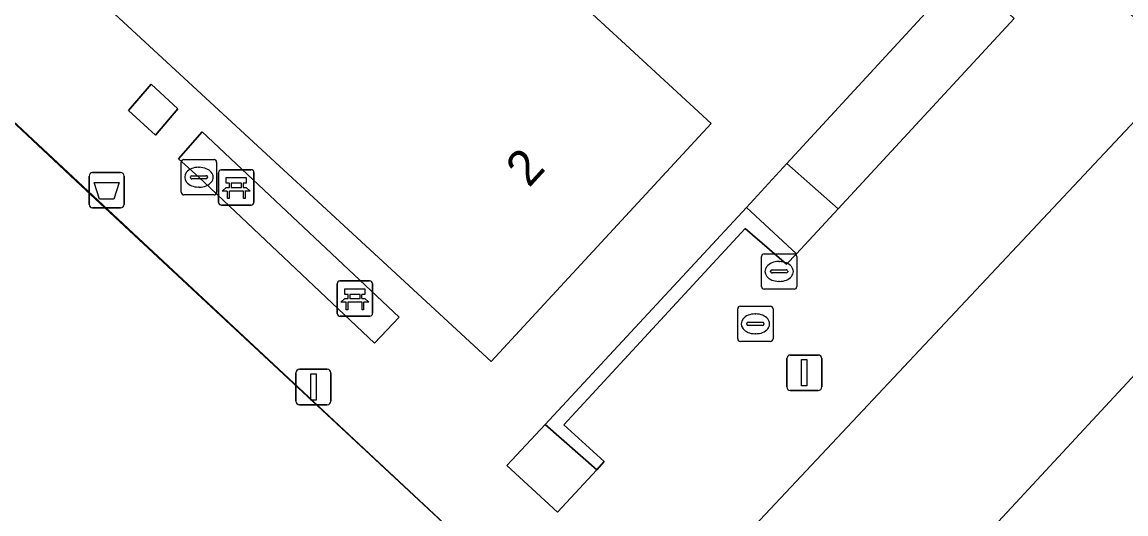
# Model space of a CAD drawing. Extents: x 155640 to 156811, y 382821 to 384049.
# Drawn here: x 156220.39 to 156251.61, y 383284.66 to 383298.57 of the extents above; entities that cross this region are included whole.
import ezdxf

# ---------------------------------------------------------------- set-up
doc = ezdxf.new("R2010")
doc.units = 0
for name, color, linetype in [('IMGEO_Afvalbak', 7, 'Continuous'), ('IMGEO_Bank', 7, 'Continuous'), ('IMGEO_Groenvoorziening', 7, 'Continuous'), ('IMGEO_Haag', 7, 'Continuous'), ('IMGEO_Hek', 7, 'Continuous'), ('IMGEO_Kolk', 7, 'Continuous'), ('IMGEO_Lichtmast', 7, 'Continuous'), ('IMGEO_Pand', 7, 'Continuous'), ('IMGEO_Pand_nummerreeks', 7, 'Continuous'), ('IMGEO_Rioolput', 7, 'Continuous'), ('IMGEO_Terreindeel_halfverhard', 7, 'Continuous'), ('IMGEO_Voetpad_op_trap', 7, 'Continuous'), ('IMGEO_Voetpad_open', 7, 'Continuous')]:
    doc.layers.add(name, color=color, linetype=linetype)

msp = doc.modelspace()

# ---------------------------------------------------------------- linework, layer by layer
at = {"layer": 'IMGEO_Afvalbak'}
for p, q in [((156222.283, 383293.417), (156222.283, 383294.217)), ((156222.283, 383294.217), (156222.283, 383293.417)), ((156222.383, 383294.317), (156223.173, 383294.317)), ((156223.173, 383294.317), (156222.383, 383294.317)), ((156223.273, 383294.217), (156223.273, 383293.417)), ((156223.273, 383293.417), (156223.273, 383294.217)), ((156223.173, 383293.317), (156222.383, 383293.317)), ((156222.383, 383293.317), (156223.173, 383293.317))]:
    msp.add_line(p, q, dxfattribs=at)
msp.add_lwpolyline([(156222.426, 383294.031), (156223.13, 383294.031), (156222.981, 383293.561), (156222.575, 383293.561), (156222.426, 383294.031)], dxfattribs=at)
for centre, start, end in [((156222.383, 383294.217), 90, 180), ((156222.383, 383294.217), 90, 180), ((156223.173, 383294.217), 0, 90), ((156223.173, 383294.217), 360, 90), ((156222.383, 383293.417), 180, 270), ((156222.383, 383293.417), 180, 270), ((156223.173, 383293.417), 270, 0), ((156223.173, 383293.417), 270, 0)]:
    msp.add_arc(centre, 0.1, start, end, dxfattribs=at)
at = {"layer": 'IMGEO_Bank'}
for p, q in [((156225.946, 383293.471), (156225.946, 383294.312)), ((156225.946, 383294.312), (156225.946, 383293.471)), ((156226.021, 383294.396), (156226.862, 383294.396)), ((156226.862, 383294.396), (156226.021, 383294.396)), ((156226.946, 383294.321), (156226.946, 383293.48)), ((156226.946, 383293.48), (156226.946, 383294.321)), ((156226.255, 383293.902), (156226.255, 383294.008)), ((156226.299, 383294.008), (156226.299, 383293.902)), ((156226.587, 383294.014), (156226.305, 383294.014)), ((156226.305, 383293.896), (156226.587, 383293.896)), ((156226.593, 383293.902), (156226.593, 383294.008)), ((156226.637, 383294.008), (156226.637, 383293.902)), ((156226.643, 383293.794), (156226.25, 383293.794)), ((156226.871, 383293.396), (156226.03, 383293.396)), ((156226.03, 383293.396), (156226.871, 383293.396)), ((156229.301, 383290.328), (156229.301, 383291.169)), ((156229.301, 383291.169), (156229.301, 383290.328)), ((156229.376, 383291.253), (156230.217, 383291.253)), ((156230.217, 383291.253), (156229.376, 383291.253)), ((156230.301, 383291.178), (156230.301, 383290.337)), ((156230.301, 383290.337), (156230.301, 383291.178)), ((156229.61, 383290.759), (156229.61, 383290.865)), ((156229.654, 383290.865), (156229.654, 383290.759)), ((156229.942, 383290.871), (156229.66, 383290.871)), ((156229.948, 383290.759), (156229.948, 383290.865)), ((156229.992, 383290.865), (156229.992, 383290.759)), ((156229.998, 383290.651), (156229.605, 383290.651)), ((156229.66, 383290.753), (156229.942, 383290.753)), ((156230.226, 383290.253), (156229.385, 383290.253)), ((156229.385, 383290.253), (156230.226, 383290.253))]:
    msp.add_line(p, q, dxfattribs=at)
for points in [[(156226.193, 383293.794), (156226.051, 383293.794), (156226.163, 383293.896), (156226.249, 383293.896)], [(156226.249, 383294.014), (156226.163, 383294.014), (156226.163, 383294.175), (156226.726, 383294.175), (156226.726, 383294.014), (156226.643, 383294.014)], [(156226.643, 383293.896), (156226.726, 383293.896), (156226.838, 383293.794), (156226.699, 383293.794)], [(156226.243, 383293.787), (156226.243, 383293.58), (156226.2, 383293.58), (156226.2, 383293.787)], [(156226.693, 383293.787), (156226.693, 383293.58), (156226.649, 383293.58), (156226.649, 383293.787)], [(156229.604, 383290.871), (156229.518, 383290.871), (156229.518, 383291.032), (156230.081, 383291.032), (156230.081, 383290.871), (156229.998, 383290.871)], [(156229.548, 383290.651), (156229.406, 383290.651), (156229.518, 383290.753), (156229.604, 383290.753)], [(156229.598, 383290.644), (156229.598, 383290.437), (156229.555, 383290.437), (156229.555, 383290.644)], [(156229.998, 383290.753), (156230.081, 383290.753), (156230.193, 383290.651), (156230.054, 383290.651)], [(156230.048, 383290.644), (156230.048, 383290.437), (156230.004, 383290.437), (156230.004, 383290.644)]]:
    msp.add_lwpolyline(points, dxfattribs=at)
for centre, radius, start, end in [((156226.024, 383294.318), 0.0779, 92.4484, 184.2845), ((156226.024, 383294.318), 0.0779, 92.4484, 184.2845), ((156226.868, 383294.318), 0.0779, 2.4484, 94.2845), ((156226.868, 383294.318), 0.0779, 2.4484, 94.2845), ((156226.248, 383294.007), 0.00671, 2.8957, 87.1043), ((156226.248, 383293.903), 0.00671, 272.8957, 357.1043), ((156226.305, 383294.007), 0.00671, 92.8957, 177.1043), ((156226.305, 383293.903), 0.00671, 182.8957, 267.1043), ((156226.587, 383294.007), 0.00671, 2.8957, 87.1043), ((156226.587, 383293.903), 0.00671, 272.8957, 357.1043), ((156226.644, 383294.007), 0.00671, 92.8957, 177.1043), ((156226.644, 383293.903), 0.00671, 182.8957, 267.1043), ((156226.193, 383293.787), 0.00671, 2.8957, 87.1043), ((156226.25, 383293.787), 0.00671, 92.8957, 177.1043), ((156226.642, 383293.787), 0.00671, 2.8957, 87.1043), ((156226.699, 383293.787), 0.00671, 92.8957, 177.1043), ((156226.024, 383293.474), 0.0779, 182.4484, 274.2845), ((156226.024, 383293.474), 0.0779, 182.4484, 274.2845), ((156226.868, 383293.474), 0.0779, 272.4484, 4.2845), ((156226.868, 383293.474), 0.0779, 272.4484, 4.2845), ((156229.379, 383291.175), 0.0779, 92.4484, 184.2845), ((156229.379, 383291.175), 0.0779, 92.4484, 184.2845), ((156230.223, 383291.175), 0.0779, 2.4484, 94.2845), ((156230.223, 383291.175), 0.0779, 2.4484, 94.2845), ((156229.603, 383290.864), 0.00671, 2.8957, 87.1043), ((156229.603, 383290.76), 0.00671, 272.8957, 357.1043), ((156229.66, 383290.864), 0.00671, 92.8957, 177.1043), ((156229.66, 383290.76), 0.00671, 182.8957, 267.1043), ((156229.942, 383290.864), 0.00671, 2.8957, 87.1043), ((156229.942, 383290.76), 0.00671, 272.8957, 357.1043), ((156229.999, 383290.864), 0.00671, 92.8957, 177.1043), ((156229.999, 383290.76), 0.00671, 182.8957, 267.1043), ((156229.548, 383290.644), 0.00671, 2.8957, 87.1043), ((156229.605, 383290.644), 0.00671, 92.8957, 177.1043), ((156229.997, 383290.644), 0.00671, 2.8957, 87.1043), ((156230.054, 383290.644), 0.00671, 92.8957, 177.1043), ((156229.379, 383290.331), 0.0779, 182.4484, 274.2845), ((156229.379, 383290.331), 0.0779, 182.4484, 274.2845), ((156230.223, 383290.331), 0.0779, 272.4484, 4.2845), ((156230.223, 383290.331), 0.0779, 272.4484, 4.2845)]:
    msp.add_arc(centre, radius, start, end, dxfattribs=at)
at = {"layer": 'IMGEO_Groenvoorziening'}
for points in [[(156246.051, 383298.946), (156242.012, 383294.574), (156243.464, 383293.287), (156248.449, 383298.674), (156247.041, 383299.984)], [(156242.291, 383292.016), (156240.872, 383293.328), (156235.177, 383287.192), (156236.64, 383285.907), (156236.846, 383286.147), (156235.707, 383287.185), (156240.833, 383292.73), (156242.011, 383291.724)]]:
    msp.add_lwpolyline(points, close=True, dxfattribs=at)
at = {"layer": 'IMGEO_Haag'}
msp.add_lwpolyline([(156242.291, 383292.016), (156240.872, 383293.328), (156235.177, 383287.192), (156236.64, 383285.907), (156236.846, 383286.147), (156235.707, 383287.185), (156240.833, 383292.73), (156242.011, 383291.724)], close=True, dxfattribs=at)
at = {"layer": 'IMGEO_Hek'}
msp.add_lwpolyline([(156214.588, 383300.953), (156234.882, 383282.008)], dxfattribs=at)
at = {"layer": 'IMGEO_Kolk'}
for p, q in [((156224.89, 383293.759), (156224.89, 383294.611)), ((156224.965, 383294.685), (156225.817, 383294.685)), ((156225.891, 383294.611), (156225.891, 383293.759)), ((156225.149, 383294.179), (156225.149, 383294.191)), ((156225.192, 383294.228), (156225.59, 383294.228)), ((156225.378, 383294.465), (156225.403, 383294.465)), ((156225.633, 383294.191), (156225.633, 383294.179)), ((156225.587, 383294.142), (156225.189, 383294.142)), ((156225.401, 383293.905), (156225.376, 383293.905)), ((156225.817, 383293.685), (156224.965, 383293.685)), ((156241.373, 383292.019), (156242.225, 383292.019)), ((156241.298, 383291.093), (156241.298, 383291.945)), ((156241.786, 383291.799), (156241.811, 383291.799)), ((156242.299, 383291.945), (156242.299, 383291.093)), ((156241.557, 383291.513), (156241.557, 383291.525)), ((156241.995, 383291.476), (156241.597, 383291.476)), ((156241.6, 383291.562), (156241.998, 383291.562)), ((156242.041, 383291.525), (156242.041, 383291.513)), ((156241.809, 383291.239), (156241.784, 383291.239)), ((156242.225, 383291.019), (156241.373, 383291.019))]:
    msp.add_line(p, q, dxfattribs=at)
for points in [[(156224.89, 383293.759), (156224.89, 383294.611)], [(156224.965, 383294.685), (156225.817, 383294.685)], [(156225.891, 383294.611), (156225.891, 383293.759)], [(156225.817, 383293.685), (156224.965, 383293.685)], [(156241.373, 383292.019), (156242.225, 383292.019)], [(156241.298, 383291.093), (156241.298, 383291.945)], [(156242.299, 383291.945), (156242.299, 383291.093)], [(156242.225, 383291.019), (156241.373, 383291.019)]]:
    msp.add_lwpolyline(points, dxfattribs=at)
for centre, radius, start, end in [((156224.967, 383294.609), 0.0765, 91.552, 178.448), ((156224.967, 383294.609), 0.0765, 91.552, 178.448), ((156225.815, 383294.609), 0.0765, 1.552, 88.448), ((156225.815, 383294.609), 0.0765, 1.552, 88.448), ((156225.189, 383294.188), 0.0403, 85.8775, 175.7526), ((156225.594, 383294.19), 0.0386, 1.7309, 96.639), ((156225.186, 383294.178), 0.0366, 178.938, 274.7102), ((156225.59, 383294.185), 0.043, 264.8664, 352.4533), ((156224.967, 383293.761), 0.0765, 181.552, 268.448), ((156224.967, 383293.761), 0.0765, 181.552, 268.448), ((156225.815, 383293.761), 0.0765, 271.552, 358.448), ((156225.815, 383293.761), 0.0765, 271.552, 358.448), ((156241.375, 383291.943), 0.0765, 91.552, 178.448), ((156241.375, 383291.943), 0.0765, 91.552, 178.448), ((156242.223, 383291.943), 0.0765, 1.552, 88.448), ((156242.223, 383291.943), 0.0765, 1.552, 88.448), ((156241.597, 383291.522), 0.0403, 85.8775, 175.7526), ((156241.594, 383291.512), 0.0366, 178.938, 274.7102), ((156241.998, 383291.519), 0.043, 264.8664, 352.4533), ((156242.002, 383291.524), 0.0386, 1.7309, 96.639), ((156241.375, 383291.095), 0.0765, 181.552, 268.448), ((156241.375, 383291.095), 0.0765, 181.552, 268.448), ((156242.223, 383291.095), 0.0765, 271.552, 358.448), ((156242.223, 383291.095), 0.0765, 271.552, 358.448)]:
    msp.add_arc(centre, radius, start, end, dxfattribs=at)
for centre, major_axis, ratio, start_param, end_param in [((156225.377, 383294.185), (-0.387, 0.002), 0.722429, 4.712389, 7.853982), ((156225.402, 383294.185), (-0.39, 0.002), 0.717154, 1.570796, 4.712389), ((156241.785, 383291.519), (-0.387, 0.002), 0.722429, 4.712389, 7.853982), ((156241.81, 383291.519), (-0.39, 0.002), 0.717154, 1.570796, 4.712389)]:
    msp.add_ellipse(centre, major_axis=major_axis, ratio=ratio, start_param=start_param, end_param=end_param, dxfattribs=at)
at = {"layer": 'IMGEO_Lichtmast'}
for p, q in [((156242.014, 383288.256), (156242.014, 383289.056)), ((156242.014, 383289.056), (156242.014, 383288.256)), ((156242.114, 383289.156), (156242.904, 383289.156)), ((156242.904, 383289.156), (156242.114, 383289.156)), ((156243.004, 383289.056), (156243.004, 383288.256)), ((156243.004, 383288.256), (156243.004, 383289.056)), ((156228.131, 383287.852), (156228.131, 383288.652)), ((156228.131, 383288.652), (156228.131, 383287.852)), ((156228.231, 383288.752), (156229.021, 383288.752)), ((156229.021, 383288.752), (156228.231, 383288.752)), ((156229.121, 383288.652), (156229.121, 383287.852)), ((156229.121, 383287.852), (156229.121, 383288.652)), ((156242.904, 383288.156), (156242.114, 383288.156)), ((156242.114, 383288.156), (156242.904, 383288.156)), ((156229.021, 383287.752), (156228.231, 383287.752)), ((156228.231, 383287.752), (156229.021, 383287.752))]:
    msp.add_line(p, q, dxfattribs=at)
for points in [[(156242.434, 383289.031), (156242.584, 383289.031), (156242.584, 383288.281), (156242.434, 383288.281), (156242.434, 383289.031)], [(156228.551, 383288.627), (156228.701, 383288.627), (156228.701, 383287.877), (156228.551, 383287.877), (156228.551, 383288.627)]]:
    msp.add_lwpolyline(points, dxfattribs=at)
for centre, start, end in [((156242.114, 383289.056), 90, 180), ((156242.114, 383289.056), 90, 180), ((156242.904, 383289.056), 0, 90), ((156242.904, 383289.056), 360, 90), ((156228.231, 383288.652), 90, 180), ((156228.231, 383288.652), 90, 180), ((156229.021, 383288.652), 0, 90), ((156229.021, 383288.652), 360, 90), ((156242.114, 383288.256), 180, 270), ((156242.114, 383288.256), 180, 270), ((156242.904, 383288.256), 270, 0), ((156242.904, 383288.256), 270, 0), ((156228.231, 383287.852), 180, 270), ((156228.231, 383287.852), 180, 270), ((156229.021, 383287.852), 270, 0), ((156229.021, 383287.852), 270, 0)]:
    msp.add_arc(centre, 0.1, start, end, dxfattribs=at)
at = {"layer": 'IMGEO_Pand'}
msp.add_lwpolyline([(156230.318, 383303.16), (156230.248, 383303.085), (156228.254, 383304.935), (156222.769, 383299.019), (156233.654, 383288.973), (156239.878, 383295.706), (156237.342, 383298.044), (156232.207, 383302.778), (156231.102, 383303.797), (156230.424, 383303.062)], close=True, dxfattribs=at)
at = {"layer": 'IMGEO_Rioolput'}
for p, q in [((156240.626, 383289.612), (156240.626, 383290.464)), ((156240.701, 383290.538), (156241.553, 383290.538)), ((156241.627, 383290.464), (156241.627, 383289.612)), ((156241.114, 383290.318), (156241.139, 383290.318)), ((156240.885, 383290.032), (156240.885, 383290.044)), ((156241.323, 383289.995), (156240.925, 383289.995)), ((156240.928, 383290.081), (156241.326, 383290.081)), ((156241.369, 383290.044), (156241.369, 383290.032)), ((156241.553, 383289.538), (156240.701, 383289.538)), ((156241.137, 383289.758), (156241.112, 383289.758))]:
    msp.add_line(p, q, dxfattribs=at)
for points in [[(156240.626, 383289.612), (156240.626, 383290.464)], [(156240.701, 383290.538), (156241.553, 383290.538)], [(156241.627, 383290.464), (156241.627, 383289.612)], [(156241.553, 383289.538), (156240.701, 383289.538)]]:
    msp.add_lwpolyline(points, dxfattribs=at)
for centre, radius, start, end in [((156240.703, 383290.462), 0.0765, 91.552, 178.448), ((156240.703, 383290.462), 0.0765, 91.552, 178.448), ((156241.551, 383290.462), 0.0765, 1.552, 88.448), ((156241.551, 383290.462), 0.0765, 1.552, 88.448), ((156240.925, 383290.041), 0.0403, 85.8775, 175.7526), ((156240.922, 383290.031), 0.0366, 178.938, 274.7102), ((156241.326, 383290.038), 0.043, 264.8664, 352.4533), ((156241.33, 383290.043), 0.0386, 1.7309, 96.639), ((156240.703, 383289.614), 0.0765, 181.552, 268.448), ((156240.703, 383289.614), 0.0765, 181.552, 268.448), ((156241.551, 383289.614), 0.0765, 271.552, 358.448), ((156241.551, 383289.614), 0.0765, 271.552, 358.448)]:
    msp.add_arc(centre, radius, start, end, dxfattribs=at)
for centre, major_axis, ratio, start_param, end_param in [((156241.113, 383290.038), (-0.387, 0.002), 0.722429, 4.712389, 7.853982), ((156241.138, 383290.038), (-0.39, 0.002), 0.717154, 1.570796, 4.712389)]:
    msp.add_ellipse(centre, major_axis=major_axis, ratio=ratio, start_param=start_param, end_param=end_param, dxfattribs=at)
at = {"layer": 'IMGEO_Terreindeel_halfverhard'}
msp.add_lwpolyline([(156224.158, 383270.431), (156234.882, 383282.008), (156222.047, 383293.953), (156214.588, 383300.953), (156207.982, 383307.154), (156184.491, 383281.756), (156211.6, 383256.492)], close=True, dxfattribs=at)
at = {"layer": 'IMGEO_Voetpad_op_trap'}
for points in [[(156242.012, 383294.574), (156240.872, 383293.328), (156242.291, 383292.016), (156243.464, 383293.287)], [(156235.177, 383287.192), (156234.099, 383286.031), (156235.527, 383284.709), (156236.64, 383285.907)]]:
    msp.add_lwpolyline(points, close=True, dxfattribs=at)
at = {"layer": 'IMGEO_Voetpad_open'}
for points in [[(156261.799, 383336.653), (156274.609, 383324.672), (156275.621, 383323.734), (156276.778, 383322.662), (156253.325, 383297.342), (156237.042, 383279.998), (156228.361, 383270.65), (156227.241, 383271.705), (156226.054, 383270.555), (156225.119, 383269.532), (156229.968, 383265.006), (156256.953, 383294.104), (156280.457, 383319.447), (156281.847, 383318.161), (156282.545, 383317.515), (156302.787, 383298.786), (156309.263, 383292.789), (156312.61, 383296.315), (156306.117, 383302.301), (156283.797, 383323.079), (156283.323, 383323.478), (156283.659, 383323.836), (156288.244, 383328.729)], [(156214.588, 383300.953), (156222.047, 383293.953), (156234.882, 383282.008), (156235.974, 383280.991), (156237.042, 383279.998), (156253.325, 383297.342), (156251.825, 383298.707), (156251.071, 383299.393), (156238.206, 383311.377), (156236.946, 383312.574), (156224.225, 383324.632), (156222.608, 383322.892), (156226.17, 383319.562), (156223.763, 383316.913), (156223.839, 383316.842), (156224.38, 383316.337), (156221.415, 383313.127), (156214.509, 383305.649)], [(156248.449, 383298.674), (156243.464, 383293.287), (156242.291, 383292.016), (156242.011, 383291.724), (156240.833, 383292.73), (156235.707, 383287.185), (156236.846, 383286.147), (156236.64, 383285.907), (156235.527, 383284.709), (156234.099, 383286.031), (156235.177, 383287.192), (156240.872, 383293.328), (156242.012, 383294.574), (156246.051, 383298.946)]]:
    msp.add_lwpolyline(points, dxfattribs=at)
for points in [[(156237.342, 383298.044), (156239.878, 383295.706), (156233.654, 383288.973), (156222.769, 383299.019), (156215.481, 383305.745), (156221.676, 383312.487), (156229.087, 383305.655), (156228.409, 383304.919), (156230.318, 383303.16), (156230.424, 383303.062), (156231.102, 383303.797), (156232.207, 383302.778)], [(156223.394, 383296.071), (156224.166, 383295.376), (156224.798, 383296.115), (156224.037, 383296.818)], [(156224.166, 383295.376), (156223.394, 383296.071), (156224.037, 383296.818), (156224.798, 383296.115)], [(156225.486, 383295.467), (156224.813, 383294.706), (156225.392, 383294.186), (156230.356, 383289.496), (156231.052, 383290.231)], [(156231.052, 383290.231), (156230.356, 383289.496), (156225.392, 383294.186), (156224.813, 383294.706), (156225.486, 383295.467)], [(156259.057, 383292.16), (156258.255, 383292.901), (156256.953, 383294.104), (156229.968, 383265.006), (156230.078, 383264.903), (156230.326, 383265.146), (156232.367, 383263.357), (156255.829, 383288.633), (156268.652, 383276.721), (156269.946, 383275.518), (156276.075, 383269.864), (156278.927, 383272.957), (156285.653, 383266.679), (156286.105, 383267.166)]]:
    msp.add_lwpolyline(points, close=True, dxfattribs=at)

# ---------------------------------------------------------------- texts
at = {"layer": 'IMGEO_Pand_nummerreeks'}
msp.add_text('2', height=1, rotation=47.5562, dxfattribs=at).set_placement((156234.723, 383293.866))

doc.saveas('drawing.dxf')
